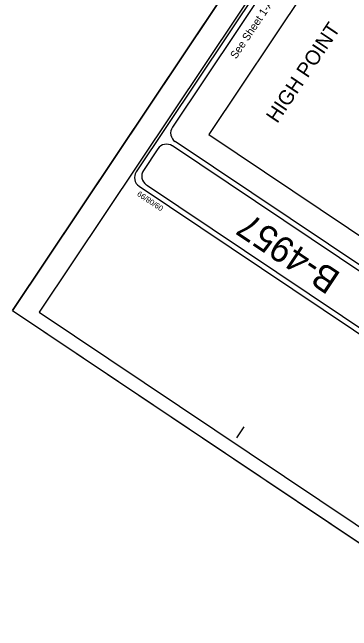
# Model space of a CAD drawing. Extents: x 1715610 to 1720914, y 798298 to 802505.
# Drawn here: x 1715998 to 1716488, y 799944 to 800836 of the extents above; entities that cross this region are included whole.
import ezdxf

# ---------------------------------------------------------------- set-up
doc = ezdxf.new("R2010")
doc.units = 0
for name, color, linetype in [('Prop DSN Text', 7, 'Continuous'), ('Sheet Cutting Line CELL', 7, 'Continuous'), ('Sheet Plot Border Inside CELL', 7, 'Continuous'), ('Sheet Plot Border Outside CELL', 7, 'Continuous'), ('Sheet Title CELL', 7, 'Continuous')]:
    doc.layers.add(name, color=color, linetype=linetype)

msp = doc.modelspace()

# ---------------------------------------------------------------- linework, layer by layer
at = {"layer": 'Prop DSN Text'}
msp.add_lwpolyline([(1716644.27, 800417.02), (1716922.46, 800832.66), (1716560.18, 801075.15), (1716281.98, 800659.5)], close=True, dxfattribs=at)
at = {"layer": 'Sheet Cutting Line CELL'}
for q in [(1717403.5, 802505.18), (1717369.67, 799488.23)]:
    msp.add_line((1715998.48, 800405.98), q, dxfattribs=at)
at = {"layer": 'Sheet Plot Border Inside CELL'}
msp.add_lwpolyline([(1717352.55, 799523.15), (1718742.97, 801600.53), (1717427.73, 802480.84), (1716037.32, 800403.46)], close=True, dxfattribs=at)
at = {"layer": 'Sheet Plot Border Outside CELL'}
msp.add_lwpolyline([(1717403.5, 802505.18), (1715998.48, 800405.98), (1717369.67, 799488.23), (1718774.69, 801587.42)], close=True, dxfattribs=at)
at = {"layer": 'Sheet Title CELL'}
for p, q in [((1717500.86, 799792.1), (1716229.38, 800643.12)), ((1717274.42, 799952.69), (1716233.55, 800649.36)), ((1716322.44, 800222.55), (1716332.87, 800238.13)), ((1716322.44, 800222.55), (1716332.87, 800238.13))]:
    msp.add_line(p, q, dxfattribs=at)
for points in [[(1717412.15, 802450.68), (1716177.3, 800605.76)], [(1717414.2, 802440.26), (1716229.46, 800670.17)], [(1716208.59, 800638.99), (1716187.71, 800607.84)], [(1716181.43, 800584.97), (1717465.38, 799725.6)], [(1716181.43, 800584.97), (1717465.38, 799725.6)], [(1716191.85, 800587.04), (1717463.32, 799736.01)]]:
    msp.add_lwpolyline(points, dxfattribs=at)
for centre, start, end in [((1716241.84, 800661.86), 146.20506, 236.20506), ((1716220.99, 800630.7), 56.20506, 146.20506), ((1716189.72, 800597.48), 146.20506, 236.20506), ((1716200.13, 800599.54), 146.20506, 236.20506)]:
    msp.add_arc(centre, 15, start, end, dxfattribs=at)

# ---------------------------------------------------------------- texts
at = {"layer": 'Prop DSN Text'}
msp.add_text('HIGH POINT', height=21.17, rotation=56.20506, dxfattribs=at).set_placement((1716380.74, 800674.71))
at = {"layer": 'Sheet Title CELL'}
for s, height, rotation, p in [('See Sheet 1-A For Index of Sheets', 11.25, 56.20506, (1716321.28, 800767.71)), ('09/08/99', 7.875, 146.20506, (1716217.21, 800555.16)), ('B-4957', 37.5, 146.20506, (1716474.11, 800458.77))]:
    msp.add_text(s, height=height, rotation=rotation, dxfattribs=at).set_placement(p)

doc.saveas('drawing.dxf')
